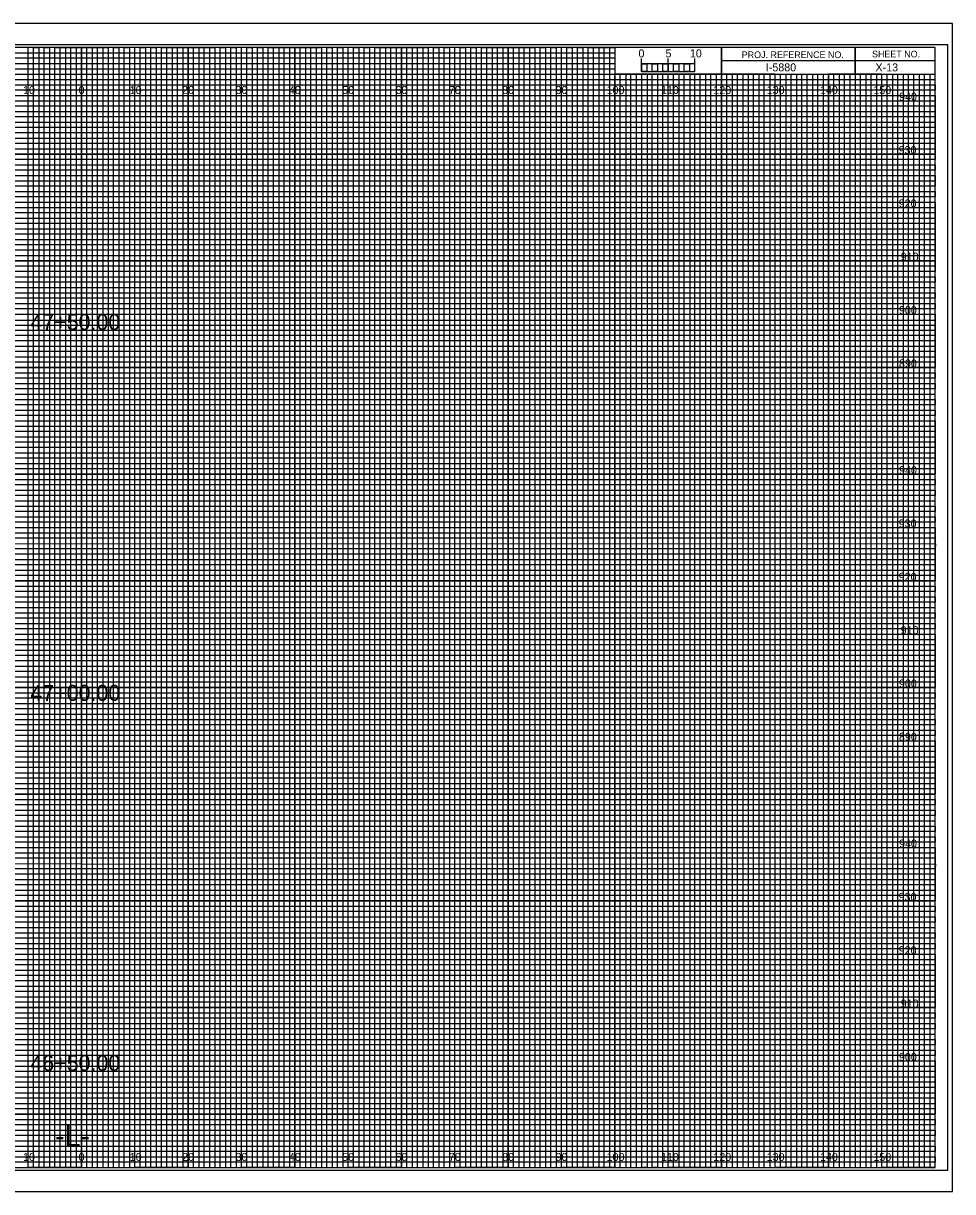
# Model space of a CAD drawing. Extents: x -13 to 323, y -4 to 3074.
# Drawn here: x 149.1 to 323.3, y 2415.5 to 2634.5 of the extents above; entities that cross this region are included whole.
import ezdxf

# ---------------------------------------------------------------- set-up
doc = ezdxf.new("R2010")
doc.units = 0
for name, color, linetype in [('Prop XS Alignment Label', 7, 'Continuous'), ('Prop XS Bar Scale Labels', 7, 'Continuous'), ('Prop XS Elevation Labels', 7, 'Continuous'), ('Prop XS Offset Labels', 7, 'Continuous'), ('Prop XS Project Number', 7, 'Continuous'), ('Prop XS Sheet Number', 7, 'Continuous'), ('Prop XS Station Labels', 7, 'Continuous'), ('Sheet Cross Section CELL', 7, 'Continuous'), ('Sheet Cross Section Grid Major CELL', 7, 'Continuous'), ('Sheet Cross Section Grid Middle CELL', 7, 'Continuous'), ('Sheet Cross Section Grid Minor 1 CELL', 7, 'Continuous'), ('Sheet Cross Section Grid Minor 2 CELL', 7, 'Continuous'), ('Sheet Cross Section Scale CELL', 7, 'Continuous'), ('Sheet Cutting Line CELL', 7, 'Continuous'), ('Sheet DOT Grid CELL', 7, 'Continuous'), ('Sheet Plot Border Inside CELL', 7, 'Continuous'), ('Sheet Plot Border Outside CELL', 7, 'Continuous')]:
    doc.layers.add(name, color=color, linetype=linetype)

msp = doc.modelspace()

# ---------------------------------------------------------------- linework, layer by layer
at = {"layer": 'Sheet Cross Section CELL'}
for p, q in [((305, 2630), (305, 2625)), ((305, 2625), (305, 2630)), ((280, 2627.5), (280, 2625)), ((320, 2627.49), (280, 2627.49)), ((280, 2625), (320, 2625))]:
    msp.add_line(p, q, dxfattribs=at)
for points in [[(320, 2630), (0, 2630), (0, 2420), (320, 2420)], [(280, 2630), (260, 2630), (260, 2625.03), (280, 2625.03)], [(320, 2630), (280, 2630), (280, 2625), (320, 2625)]]:
    msp.add_lwpolyline(points, close=True, dxfattribs=at)
at = {"layer": 'Sheet Cross Section Grid Major CELL'}
for p, q in [((150, 2630), (140, 2630)), ((150, 2420), (150, 2630)), ((170, 2630), (160, 2630)), ((160, 2630), (160, 2420)), ((170, 2420), (170, 2630)), ((190, 2630), (180, 2630)), ((180, 2630), (180, 2420)), ((190, 2420), (190, 2630)), ((210, 2630), (200, 2630)), ((200, 2630), (200, 2420)), ((210, 2420), (210, 2630)), ((230, 2630), (220, 2630)), ((220, 2630), (220, 2420)), ((230, 2420), (230, 2630)), ((250, 2630), (240, 2630)), ((240, 2630), (240, 2420)), ((250, 2420), (250, 2630)), ((260, 2630), (260, 2420)), ((270, 2420), (270, 2625)), ((290, 2625), (280, 2625)), ((280, 2625), (280, 2420)), ((290, 2420), (290, 2625)), ((310, 2625), (300, 2625)), ((300, 2625), (300, 2420)), ((310, 2420), (310, 2625)), ((160, 2420), (150, 2420)), ((180, 2420), (170, 2420)), ((200, 2420), (190, 2420)), ((220, 2420), (210, 2420)), ((240, 2420), (230, 2420)), ((260, 2420), (250, 2420)), ((280, 2420), (270, 2420)), ((300, 2420), (290, 2420)), ((320, 2420), (310, 2420)), ((320, 2420), (320, 2420))]:
    msp.add_line(p, q, dxfattribs=at)
for points in [[(0, 2620), (320, 2620), (320, 2610), (0, 2610)], [(0, 2600), (320, 2600), (320, 2590), (0, 2590)], [(0, 2580), (320, 2580), (320, 2570), (0, 2570)], [(0, 2560), (320, 2560), (320, 2550), (0, 2550)], [(0, 2540), (320, 2540), (320, 2530), (0, 2530)], [(0, 2520), (320, 2520), (320, 2510), (0, 2510)], [(0, 2500), (320, 2500), (320, 2490), (0, 2490)], [(0, 2480), (320, 2480), (320, 2470), (0, 2470)], [(0, 2460), (320, 2460), (320, 2450), (0, 2450)], [(0, 2440), (320, 2440), (320, 2430), (0, 2430)]]:
    msp.add_lwpolyline(points, dxfattribs=at)
at = {"layer": 'Sheet Cross Section Grid Middle CELL'}
for points in [[(145, 2420), (155, 2420), (155, 2630), (165, 2630), (165, 2420), (175, 2420), (175, 2630), (185, 2630), (185, 2420), (195, 2420), (195, 2630), (205, 2630), (205, 2420), (215, 2420), (215, 2630), (225, 2630), (225, 2420), (235, 2420), (235, 2630), (245, 2630), (245, 2420), (255, 2420), (255, 2630), (259.93, 2630), (260, 2630), (260, 2625), (264.99, 2625), (264.99, 2420), (275, 2420), (275, 2625), (285, 2625), (285, 2420), (295, 2420), (295, 2625), (305, 2625), (305, 2420), (315, 2420), (315, 2625)], [(0, 2625), (275, 2625)], [(0, 2605), (320, 2605), (320, 2615), (0, 2615)], [(0, 2585), (320, 2585), (320, 2595), (0, 2595)], [(0, 2565), (320, 2565), (320, 2575), (0, 2575)], [(0, 2545), (320, 2545), (320, 2555), (0, 2555)], [(0, 2525), (320, 2525), (320, 2535), (0, 2535)], [(0, 2505), (320, 2505), (320, 2515), (0, 2515)], [(0, 2485), (320, 2485), (320, 2495), (0, 2495)], [(0, 2465), (320, 2465), (320, 2475), (0, 2475)], [(0, 2445), (320, 2445), (320, 2455), (0, 2455)], [(0, 2425), (320, 2425), (320, 2435), (0, 2435)]]:
    msp.add_lwpolyline(points, dxfattribs=at)
at = {"layer": 'Sheet Cross Section Grid Minor 1 CELL'}
for p, q in [((0, 2629), (260, 2629)), ((260, 2629), (260, 2627.98)), ((260, 2627.98), (0, 2627.98)), ((0, 2627), (260, 2627)), ((260, 2625.89), (0, 2625.89)), ((260, 2627), (260, 2625.89)), ((0, 2624), (320, 2624))]:
    msp.add_line(p, q, dxfattribs=at)
for points in [[(0, 2623), (270, 2623), (320, 2623), (320, 2622), (0, 2622)], [(0, 2621), (320, 2621), (320, 2619), (0, 2619)], [(0, 2618), (320, 2618), (320, 2617), (0, 2616.98)], [(0, 2616), (320, 2616), (320, 2614), (0, 2614)], [(0, 2613), (320, 2613), (320, 2612), (0, 2612)], [(0, 2611), (320, 2611), (320, 2609), (0, 2609)], [(0, 2608), (320, 2608), (320, 2607), (0, 2607)], [(0, 2606), (320, 2606), (320, 2604), (0, 2604)], [(0, 2603), (320, 2603), (320, 2602), (0, 2602)], [(0, 2601), (320, 2601), (320, 2599), (0, 2599)], [(0, 2598), (320, 2598), (320, 2597), (0, 2597)], [(0, 2596), (320, 2596), (320, 2593.95), (320, 2593), (320, 2592), (0, 2592)], [(0, 2594), (320, 2594), (320, 2593), (0, 2593)], [(0, 2591), (320, 2591), (320, 2589), (0, 2589.03)], [(0, 2589.03), (320, 2589), (320, 2588), (0, 2588)], [(0, 2587), (320, 2587), (320, 2586), (0, 2586)], [(0, 2584), (320, 2584), (320, 2583), (0, 2583)], [(0, 2582), (320, 2582), (320, 2581), (0, 2581)], [(-0.07, 2578.89), (320, 2578.89), (320, 2577.88), (-0.07, 2577.88)], [(0, 2577), (320, 2577), (320, 2576), (0, 2576)], [(0, 2574), (320, 2574), (320, 2573), (0, 2573)], [(0, 2572), (320, 2572), (320, 2571), (0, 2571)], [(0, 2569), (320, 2569), (320, 2568), (0, 2568)], [(0, 2567), (320, 2567), (320, 2566), (0, 2566)], [(0, 2564), (320, 2564), (320, 2563), (0, 2563)], [(0, 2562), (320, 2562), (320, 2561), (0, 2561)], [(0, 2559), (320, 2559), (319.99, 2557.98), (0, 2558)], [(0, 2557), (320, 2557), (320, 2556), (0, 2556)], [(0, 2554), (320, 2554), (320, 2553), (0, 2553)], [(0, 2552), (320, 2552), (320, 2551), (0, 2551)], [(0, 2549), (320, 2549), (320, 2548), (0, 2548)], [(0, 2547), (320, 2547), (320, 2546), (0, 2546)], [(0, 2544), (320, 2544), (320, 2543), (0, 2543)], [(0, 2542), (320, 2542), (320, 2541), (0, 2541)], [(0, 2539), (320, 2539), (320, 2538), (0, 2538)], [(0, 2536.99), (320.07, 2536.91), (320, 2536), (0, 2536)], [(0, 2534), (320, 2534), (320, 2533), (0, 2533)], [(0, 2532), (320, 2532), (320, 2531), (0, 2531)], [(0, 2529), (320, 2529), (320, 2528), (0, 2528)], [(0, 2527), (320, 2527), (320, 2526), (0, 2526)], [(0, 2524), (320, 2524), (320, 2523), (0, 2523)], [(0, 2522), (320, 2522), (320, 2521), (0, 2521)], [(0, 2519), (320, 2519), (320, 2518), (0, 2518)], [(0, 2517), (320, 2517), (320, 2516), (0, 2516)], [(0, 2514), (320, 2514), (320, 2513), (0, 2513)], [(0, 2512), (320, 2512), (320, 2511), (0, 2511)], [(0, 2509), (320, 2509), (320, 2508), (0, 2508)], [(0, 2507), (320, 2507), (320, 2506), (0, 2506)], [(0, 2504), (320, 2504), (320, 2503), (0, 2503)], [(0, 2502), (320, 2502), (320, 2501), (0, 2501)], [(0, 2499), (320, 2499), (319.99, 2497.98), (0, 2498)], [(0, 2497), (320, 2497), (320, 2496), (0, 2496)], [(0, 2494), (320, 2494), (320, 2493), (0, 2493)], [(0, 2492), (320, 2492), (320, 2491), (0, 2491)], [(0, 2489), (320, 2489), (320, 2488), (0, 2488)], [(0, 2487), (320, 2487), (320, 2486), (0, 2486)], [(0, 2484), (320, 2484), (320, 2483), (0, 2483)], [(0, 2482), (320, 2482), (320, 2481), (0, 2481)], [(0, 2479), (320, 2479), (320, 2478), (0, 2478)], [(0, 2476.99), (320.07, 2476.91), (320, 2476), (0, 2476)], [(0, 2474), (320, 2474), (320, 2473), (0, 2473)], [(0, 2472), (320, 2472), (320, 2471), (0, 2471)], [(0, 2469), (320, 2469), (320, 2468), (0, 2468)], [(0, 2467), (320, 2467), (320, 2466), (0, 2466)], [(0, 2464), (320, 2464), (320, 2463), (0, 2463)], [(0, 2462), (320, 2462), (320, 2461), (0, 2461)], [(0, 2459), (320, 2459), (320, 2458), (0, 2458)], [(0, 2457), (320, 2457), (320, 2456), (0, 2456)], [(0, 2454), (320, 2454), (320, 2453), (0, 2453)], [(0, 2452), (320, 2452), (320, 2451), (0, 2451)], [(0, 2449), (320, 2449), (320, 2448), (0, 2448)], [(0, 2447), (320, 2447), (320, 2446), (0, 2446)], [(0, 2444), (320, 2444), (320, 2443), (0, 2443)], [(0, 2442), (320, 2442), (320, 2441), (0, 2441)], [(0, 2439), (320, 2439), (320, 2438), (0, 2438)], [(0, 2437), (320, 2437), (320, 2436), (0, 2436)], [(0, 2434), (320, 2434), (320, 2433), (0, 2433)], [(0, 2432), (320, 2432), (320, 2431), (0, 2431)], [(0, 2429), (320, 2429), (320, 2428), (0, 2428)], [(0, 2427), (320, 2427), (320, 2426), (0, 2426)], [(0, 2424), (320, 2424), (320, 2423), (0, 2423)], [(0, 2422), (320, 2422), (320, 2421), (0, 2421)]]:
    msp.add_lwpolyline(points, dxfattribs=at)
at = {"layer": 'Sheet Cross Section Grid Minor 2 CELL'}
for p, q in [((267, 2625), (266.01, 2625)), ((266.01, 2625), (266.01, 2420)), ((267, 2420), (267, 2625)), ((269, 2625), (268, 2625)), ((268, 2625), (268, 2420)), ((269, 2420), (269, 2625)), ((266.01, 2420), (265, 2420)), ((268, 2420), (267, 2420))]:
    msp.add_line(p, q, dxfattribs=at)
for points in [[(150, 2420), (151, 2420), (151, 2630), (152, 2630), (152, 2420)], [(152, 2420), (153, 2420), (153, 2630), (154, 2630), (154, 2420)], [(155, 2420), (156, 2420), (156, 2630), (157, 2630), (157, 2420)], [(157, 2420), (158, 2420), (158, 2630), (159, 2630), (159, 2420)], [(160, 2420), (161, 2420), (161, 2630), (162, 2630), (162, 2420)], [(162, 2420), (163, 2420), (163, 2630), (164, 2630), (164, 2420)], [(165, 2420), (166, 2420), (166, 2630), (167, 2630), (167, 2420)], [(167, 2420), (168, 2420), (168, 2630), (169, 2630), (169, 2420)], [(170, 2420), (171, 2420), (171, 2630), (172, 2630), (172, 2420)], [(172, 2420), (173, 2420), (173, 2630), (174, 2630), (174, 2420)], [(175, 2420), (176, 2420), (176, 2630), (177, 2630), (177, 2420)], [(177, 2420), (178, 2420), (178, 2630), (179, 2630), (179, 2420)], [(180, 2420), (181, 2420), (181, 2630), (182, 2630), (182, 2420)], [(182, 2420), (183, 2420), (183, 2630), (184, 2630), (184, 2420)], [(185, 2420), (186, 2420), (186, 2630), (187, 2630), (187, 2420)], [(187, 2420), (188, 2420), (188, 2630), (189, 2630), (189, 2420)], [(190, 2420), (191, 2420), (191, 2630), (192, 2630), (192, 2420)], [(192, 2420), (193, 2420), (193, 2630), (194, 2630), (194, 2420)], [(195, 2420), (196, 2420), (196, 2630), (197, 2630), (197, 2420)], [(197, 2420), (198, 2420), (198, 2630), (199, 2630), (199, 2420)], [(200, 2420), (201, 2420), (201, 2630), (202, 2630), (202, 2420)], [(202, 2420), (203, 2420), (203, 2630), (204, 2630), (204, 2420)], [(205, 2420), (206, 2420), (206, 2630), (207, 2630), (207, 2420)], [(207, 2420), (208, 2420), (208, 2630), (209, 2630), (209, 2420)], [(210, 2420), (211, 2420), (211, 2630), (212, 2630), (212, 2420)], [(212, 2420), (213, 2420), (213, 2630), (214, 2630), (214, 2420)], [(215, 2420), (216, 2420), (216, 2630), (217, 2630), (217, 2420)], [(217, 2420), (218, 2420), (218, 2630), (219, 2630), (219, 2420)], [(220, 2420), (221, 2420), (221, 2630), (222, 2630), (222, 2420)], [(222, 2420), (223, 2420), (223, 2630), (224, 2630), (224, 2420)], [(225, 2420), (226, 2420), (226, 2630), (227, 2630), (227, 2420)], [(227, 2420), (228, 2420), (228, 2630), (229, 2630), (229, 2420)], [(230, 2420), (231, 2420), (231, 2630), (232, 2630), (232, 2420)], [(232, 2420), (233, 2420), (233, 2630), (234, 2630), (234, 2420)], [(235, 2420), (236, 2420), (236, 2630), (237, 2630), (237, 2420)], [(237, 2420), (238, 2420), (238, 2630), (239, 2630), (239, 2420)], [(240, 2420), (241, 2420), (241, 2630), (242, 2630), (242, 2420)], [(242, 2420), (243, 2420), (243, 2630), (244, 2630), (244, 2420)], [(245, 2420), (246, 2420), (246, 2630), (247, 2630), (247, 2420)], [(247, 2420), (248, 2420), (248, 2630), (249, 2630), (249, 2420)], [(250, 2420), (251, 2420), (251, 2630), (252, 2630), (252, 2420)], [(252, 2420), (253, 2420), (253, 2630), (254, 2630), (254, 2420)], [(255, 2420), (256, 2420), (256, 2630), (257, 2630), (257, 2420)], [(257, 2420), (258, 2420), (258, 2630), (259, 2630), (259, 2420)], [(260, 2420), (261, 2420), (261, 2625), (262.02, 2625), (262.02, 2420)], [(262, 2420), (263, 2420), (263, 2625), (263.99, 2625), (263.99, 2420)], [(270, 2420), (270.98, 2420), (270.98, 2625), (272, 2625), (272, 2420)], [(272, 2420), (273, 2420), (273, 2625), (274.05, 2625), (274.05, 2420)], [(275, 2420), (276, 2420), (276, 2625), (277, 2625), (277, 2420)], [(277, 2420), (278, 2420), (278, 2625), (279, 2625), (279, 2420)], [(280, 2420), (281, 2420), (281, 2625), (282, 2625), (282, 2420)], [(282, 2420), (283, 2420), (283, 2625), (284, 2625), (284, 2420)], [(285, 2420), (286, 2420), (286, 2625), (287, 2625), (287, 2420)], [(287, 2420), (288, 2420), (288, 2625), (289, 2625), (289, 2420)], [(290, 2420), (291, 2420), (291, 2625), (292, 2625), (292, 2420)], [(292, 2420), (293, 2420), (293, 2625), (294, 2625), (294, 2420)], [(295, 2420), (296, 2420), (296, 2625), (297, 2625), (297, 2420)], [(297, 2420), (298, 2420), (298, 2625), (299, 2625), (299, 2420)], [(300, 2420), (301, 2420), (301, 2625), (302, 2625), (302, 2420)], [(302, 2420), (303, 2420), (303, 2625), (304, 2625), (304, 2420)], [(305, 2420), (306, 2420), (306, 2625), (307, 2625), (307, 2420)], [(307, 2420), (308, 2420), (308, 2625), (309, 2625), (309, 2420)], [(310, 2420), (311, 2420), (311, 2625), (312, 2625), (312, 2420)], [(312, 2420), (313, 2420), (313, 2625), (314, 2625), (314, 2420)], [(315, 2420), (316, 2420), (316, 2625), (317, 2625), (317, 2420)], [(317, 2420), (318, 2420), (318, 2625), (319, 2625), (319, 2420)]]:
    msp.add_lwpolyline(points, dxfattribs=at)
at = {"layer": 'Sheet Cross Section Scale CELL'}
for p, q in [((265, 2625.49), (265, 2627.9)), ((265, 2626.9), (265, 2627.9)), ((270, 2625.49), (270, 2627.9)), ((275, 2625.49), (275, 2627.9)), ((275, 2626.9), (275, 2627.9))]:
    msp.add_line(p, q, dxfattribs=at)
for points in [[(275, 2626.9), (265, 2626.9), (265, 2625.49), (275, 2625.49)], [(265, 2626.9), (266, 2626.9), (266, 2625.49), (265, 2625.49)], [(267, 2626.9), (268, 2626.9), (268, 2625.49), (267, 2625.49)], [(269, 2626.9), (270, 2626.9), (270, 2625.49), (269, 2625.49)], [(271, 2626.9), (272, 2626.9), (272, 2625.49), (271, 2625.49)], [(273, 2626.9), (274, 2626.9), (274, 2625.49), (273, 2625.49)]]:
    msp.add_lwpolyline(points, close=True, dxfattribs=at)
at = {"layer": 'Sheet Cutting Line CELL'}
for p, q in [((323.3, 2634.5), (-13.4, 2634.5)), ((-13.4, 2415.5), (323.3, 2415.5))]:
    msp.add_line(p, q, dxfattribs=at)
at = {"layer": 'Sheet DOT Grid CELL'}
for p, q in [((150, 2420), (150, 2630)), ((160, 2420), (160, 2630)), ((170, 2420), (170, 2630)), ((180, 2420), (180, 2630)), ((190, 2420), (190, 2630)), ((200, 2420), (200, 2630)), ((210, 2420), (210, 2630)), ((220, 2420), (220, 2630)), ((230, 2420), (230, 2630)), ((240, 2420), (240, 2630)), ((250, 2420), (250, 2630)), ((260, 2420), (260, 2624.69)), ((270, 2420), (270, 2624.69)), ((280, 2420), (280, 2624.69)), ((290, 2420), (290, 2624.69)), ((300, 2420), (300, 2624.69)), ((310, 2420), (310, 2624.69)), ((0, 2620), (320, 2620)), ((0, 2610), (320, 2610)), ((0, 2600), (320, 2600)), ((0, 2590), (320, 2590)), ((0, 2580), (320, 2580)), ((0, 2570), (320, 2570)), ((0, 2560), (320, 2560)), ((0, 2550), (320, 2550)), ((0, 2540), (320, 2540)), ((0, 2530), (320, 2530)), ((0, 2520), (320, 2520)), ((0, 2510), (320, 2510)), ((0, 2500), (320, 2500)), ((0, 2490), (320, 2490)), ((0, 2480), (320, 2480)), ((0, 2470), (320, 2470)), ((0, 2460), (320, 2460)), ((0, 2450), (320, 2450)), ((0, 2440), (320, 2440)), ((0, 2430), (320, 2430))]:
    msp.add_line(p, q, dxfattribs=at)
at = {"layer": 'Sheet Plot Border Inside CELL'}
msp.add_lwpolyline([(-10.8, 2419.5), (322.4, 2419.5), (322.4, 2630.5), (-10.8, 2630.5)], close=True, dxfattribs=at)
at = {"layer": 'Sheet Plot Border Outside CELL'}
msp.add_lwpolyline([(-13.4, 2415.5), (323.3, 2415.5), (323.3, 2634.5), (-13.4, 2634.5)], close=True, dxfattribs=at)

# ---------------------------------------------------------------- texts
at = {"layer": 'Prop XS Alignment Label'}
msp.add_text('-L-', height=4, dxfattribs=at).set_placement((155.06, 2424))
at = {"layer": 'Prop XS Bar Scale Labels'}
for s, p in [('5', (269.47, 2628.12)), ('10', (274.04, 2628.12))]:
    msp.add_text(s, height=1.5, dxfattribs=at).set_placement(p)
at = {"layer": 'Prop XS Elevation Labels'}
for s, p in [('940', (313.26, 2620)), ('930', (313.18, 2610)), ('920', (313.19, 2600)), ('910', (313.57, 2590)), ('900', (313.24, 2580)), ('890', (313.24, 2570)), ('940', (313.26, 2550)), ('930', (313.18, 2540)), ('920', (313.19, 2530)), ('910', (313.57, 2520)), ('900', (313.24, 2510)), ('890', (313.24, 2500)), ('940', (313.26, 2480)), ('930', (313.18, 2470)), ('920', (313.19, 2460)), ('910', (313.57, 2450)), ('900', (313.24, 2440))]:
    msp.add_text(s, height=1.5, dxfattribs=at).set_placement(p)
at = {"layer": 'Prop XS Offset Labels'}
for s, p in [('10', (149.04, 2621.25)), ('0', (159.45, 2621.25)), ('0', (159.45, 2621.25)), ('10', (169.04, 2621.25)), ('20', (178.86, 2621.25)), ('30', (188.86, 2621.25)), ('40', (198.86, 2621.25)), ('50', (208.86, 2621.25)), ('60', (218.86, 2621.25)), ('70', (228.86, 2621.25)), ('80', (238.86, 2621.25)), ('90', (248.86, 2621.25)), ('100', (258.44, 2621.25)), ('110', (268.62, 2621.25)), ('120', (278.44, 2621.25)), ('130', (288.44, 2621.25)), ('140', (298.44, 2621.25)), ('150', (308.44, 2621.25)), ('10', (149.04, 2421.25)), ('0', (159.45, 2421.25)), ('0', (159.45, 2421.25)), ('10', (169.04, 2421.25)), ('20', (178.86, 2421.25)), ('30', (188.86, 2421.25)), ('40', (198.86, 2421.25)), ('50', (208.86, 2421.25)), ('60', (218.86, 2421.25)), ('70', (228.86, 2421.25)), ('80', (238.86, 2421.25)), ('90', (248.86, 2421.25)), ('100', (258.44, 2421.25)), ('110', (268.62, 2421.25)), ('120', (278.44, 2421.25)), ('130', (288.44, 2421.25)), ('140', (298.44, 2421.25)), ('150', (308.44, 2421.25))]:
    msp.add_text(s, height=1.5, dxfattribs=at).set_placement(p)
at = {"layer": 'Prop XS Project Number'}
msp.add_text('I-5880', height=1.5, dxfattribs=at).set_placement((288.28, 2625.5))
at = {"layer": 'Prop XS Sheet Number'}
msp.add_text('X-13', height=1.5, dxfattribs=at).set_placement((308.83, 2625.5))
at = {"layer": 'Prop XS Station Labels'}
for s, p in [('47+50.00', (150.41, 2577.02)), ('47+00.00', (150.41, 2507.5)), ('46+50.00', (150.41, 2438.12))]:
    msp.add_text(s, height=3, dxfattribs=at).set_placement(p)
at = {"layer": 'Sheet Cross Section CELL'}
for s, p in [('PROJ. REFERENCE NO.', (283.77, 2627.99)), ('SHEET NO.', (308.19, 2628.12))]:
    msp.add_text(s, height=1.25, dxfattribs=at).set_placement(p)
at = {"layer": 'Sheet Cross Section Scale CELL'}
msp.add_text('0', height=1.5, dxfattribs=at).set_placement((264.41, 2628.12))

doc.saveas('drawing.dxf')
